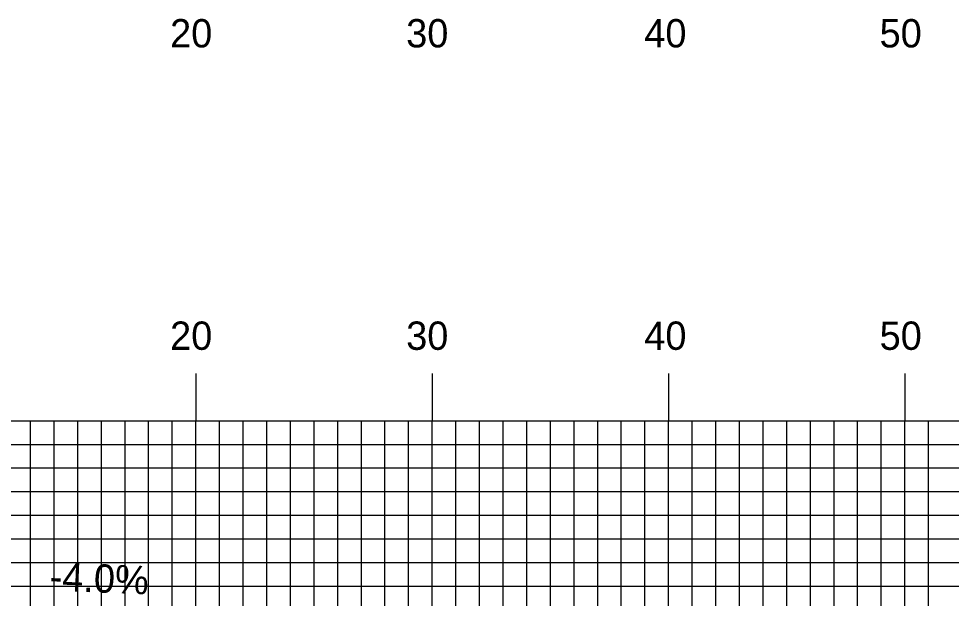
# Model space of a CAD drawing. Extents: x 1782254 to 1782597, y 442591 to 442811.
# Drawn here: x 1782431.93 to 1782471.4, y 442691.15 to 442715.68 of the extents above; entities that cross this region are included whole.
import ezdxf

# ---------------------------------------------------------------- set-up
doc = ezdxf.new("R2010")
doc.units = 0
for name, color, linetype in [('ANNOTATION', 7, 'Continuous'), ('H_V ANNOTATION', 7, 'Continuous'), ('MAJOR', 7, 'Continuous'), ('MINOR', 7, 'Continuous')]:
    doc.layers.add(name, color=color, linetype=linetype)

msp = doc.modelspace()

# ---------------------------------------------------------------- linework, layer by layer
at = {"layer": 'MAJOR'}
for p, q in [((1782439.434, 442700.669), (1782439.434, 442698.665)), ((1782449.434, 442700.669), (1782449.434, 442698.665)), ((1782459.434, 442700.669), (1782459.434, 442698.665)), ((1782469.434, 442700.669), (1782469.434, 442698.665)), ((1782279.434, 442698.665), (1782559.434, 442698.665)), ((1782279.434, 442698.665), (1782559.434, 442698.665)), ((1782439.434, 442663.665), (1782439.434, 442698.665)), ((1782449.434, 442663.665), (1782449.434, 442698.665)), ((1782459.434, 442663.665), (1782459.434, 442698.665)), ((1782469.434, 442663.665), (1782469.434, 442698.665)), ((1782279.434, 442693.665), (1782559.434, 442693.665))]:
    msp.add_line(p, q, dxfattribs=at)
at = {"layer": 'MINOR'}
for p, q in [((1782432.434, 442663.665), (1782432.434, 442698.665)), ((1782433.434, 442663.665), (1782433.434, 442698.665)), ((1782434.434, 442663.665), (1782434.434, 442698.665)), ((1782435.434, 442663.665), (1782435.434, 442698.665)), ((1782436.434, 442663.665), (1782436.434, 442698.665)), ((1782437.434, 442663.665), (1782437.434, 442698.665)), ((1782438.434, 442663.665), (1782438.434, 442698.665)), ((1782440.434, 442663.665), (1782440.434, 442698.665)), ((1782441.434, 442663.665), (1782441.434, 442698.665)), ((1782442.434, 442663.665), (1782442.434, 442698.665)), ((1782443.434, 442663.665), (1782443.434, 442698.665)), ((1782444.434, 442663.665), (1782444.434, 442698.665)), ((1782445.434, 442663.665), (1782445.434, 442698.665)), ((1782446.434, 442663.665), (1782446.434, 442698.665)), ((1782447.434, 442663.665), (1782447.434, 442698.665)), ((1782448.434, 442663.665), (1782448.434, 442698.665)), ((1782450.434, 442663.665), (1782450.434, 442698.665)), ((1782451.434, 442663.665), (1782451.434, 442698.665)), ((1782452.434, 442663.665), (1782452.434, 442698.665)), ((1782453.434, 442663.665), (1782453.434, 442698.665)), ((1782454.434, 442663.665), (1782454.434, 442698.665)), ((1782455.434, 442663.665), (1782455.434, 442698.665)), ((1782456.434, 442663.665), (1782456.434, 442698.665)), ((1782457.434, 442663.665), (1782457.434, 442698.665)), ((1782458.434, 442663.665), (1782458.434, 442698.665)), ((1782460.434, 442663.665), (1782460.434, 442698.665)), ((1782461.434, 442663.665), (1782461.434, 442698.665)), ((1782462.434, 442663.665), (1782462.434, 442698.665)), ((1782463.434, 442663.665), (1782463.434, 442698.665)), ((1782464.434, 442663.665), (1782464.434, 442698.665)), ((1782465.434, 442663.665), (1782465.434, 442698.665)), ((1782466.434, 442663.665), (1782466.434, 442698.665)), ((1782467.434, 442663.665), (1782467.434, 442698.665)), ((1782468.434, 442663.665), (1782468.434, 442698.665)), ((1782470.434, 442663.665), (1782470.434, 442698.665)), ((1782279.434, 442697.665), (1782559.434, 442697.665)), ((1782279.434, 442696.665), (1782559.434, 442696.665)), ((1782279.434, 442695.665), (1782559.434, 442695.665)), ((1782279.434, 442694.665), (1782559.434, 442694.665)), ((1782279.434, 442692.665), (1782559.434, 442692.665)), ((1782279.434, 442691.665), (1782559.434, 442691.665))]:
    msp.add_line(p, q, dxfattribs=at)

# ---------------------------------------------------------------- texts
at = {"layer": 'ANNOTATION'}
msp.add_text('-4.0%', height=1.2, rotation=357.7094, dxfattribs=at).set_placement((1782433.226, 442691.478))
at = {"layer": 'H_V ANNOTATION'}
for s, p in [('20', (1782438.342, 442714.465)), ('30', (1782448.331, 442714.465)), ('40', (1782458.406, 442714.465)), ('50', (1782468.363, 442714.465)), ('20', (1782438.342, 442701.665)), ('30', (1782448.331, 442701.665)), ('40', (1782458.406, 442701.665)), ('50', (1782468.363, 442701.665))]:
    msp.add_text(s, height=1.2, dxfattribs=at).set_placement(p)

doc.saveas('drawing.dxf')
